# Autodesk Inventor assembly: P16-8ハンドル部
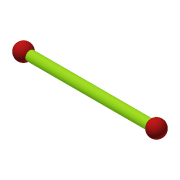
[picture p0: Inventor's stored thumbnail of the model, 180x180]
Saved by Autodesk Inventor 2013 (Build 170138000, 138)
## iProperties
Created: 2008-07
Part Number: P16-8ハンドル部
Document SubType Name: Assembly
Designer: y-shimohigashi
Author: y-shimohigashi
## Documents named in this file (3)
- C:\Users\t-komatsu\Desktop\新しいフォルダー\Inventor2013基礎コース\練習問題-16\A16-8ハンドル部.iam
- C:\Users\t-komatsu\Desktop\新しいフォルダー\Inventor2013基礎コース\練習問題-16\P16-9ハンドル.ipt
- C:\Users\t-komatsu\Desktop\新しいフォルダー\Inventor2013基礎コース\練習問題-16\P16-10ボス.ipt
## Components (3 placed, 2 different names)
1. P16-9ハンドル:1 — 挿入:1, 挿入:2
2. P16-10ボス:1 — 挿入:1
3. P16-10ボス:2 — 挿入:2
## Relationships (2: Insert 2)
- 挿入:1 [Insert]: P16-9ハンドル:1 ↔ P16-10ボス:1
- 挿入:2 [Insert]: P16-9ハンドル:1 ↔ P16-10ボス:2
